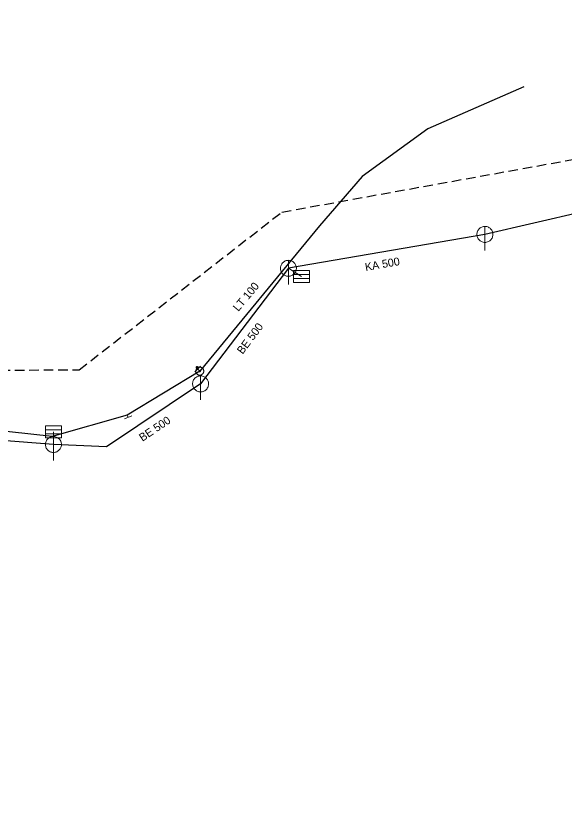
# Model space of a CAD drawing. Extents: x -687013 to -686506, y -973869 to -973672.
# Drawn here: x -686801.2 to -686732.6, y -973770.5 to -973671.6 of the extents above; entities that cross this region are included whole.
import ezdxf

# ---------------------------------------------------------------- set-up
doc = ezdxf.new("R2010")
doc.units = 0
doc.header["$LTSCALE"] = 0.4
doc.linetypes.add('MEDIUM_DASHED', pattern=[4.5, 3, -1.5])
doc.layers.add('1', color=7, linetype='Continuous')
for name, color, linetype, lineweight in [('11', 7, 'Continuous', 13), ('14', 7, 'Continuous', 25), ('17', 7, 'Continuous', 25), ('22', 7, 'Continuous', 13), ('34', 7, 'Continuous', 13), ('47', 7, 'Continuous', 13), ('63', 7, 'MEDIUM_DASHED', 25), ('9', 7, 'Continuous', 13)]:
    doc.layers.add(name, color=color, linetype=linetype, lineweight=lineweight)

msp = doc.modelspace()

# ---------------------------------------------------------------- linework, layer by layer
at = {"layer": '11'}
for p, q in [((-686765.44, -973704.18), (-686767.08, -973703.16)), ((-686796.46, -973723.59), (-686796.46, -973725.17))]:
    msp.add_line(p, q, dxfattribs=at)
at = {"layer": '14'}
for p, q in [((-686704.809, -973690.17), (-686742.511, -973698.919)), ((-686742.511, -973698.919), (-686767.08, -973703.16)), ((-686767.079, -973703.16), (-686778.059, -973717.6)), ((-686796.46, -973725.17), (-686811.199, -973724.039))]:
    msp.add_line(p, q, dxfattribs=at)
at = {"layer": '14', "lineweight": 13}
for p, q in [((-686778.409, -973715.759), (-686778.489, -973715.559)), ((-686778.16, -973716.008), (-686778.409, -973715.759)), ((-686787.234, -973721.504), (-686787.109, -973721.78))]:
    msp.add_line(p, q, dxfattribs=at)
at = {"layer": '14'}
msp.add_lwpolyline([(-686778.059, -973717.6), (-686789.822, -973725.456), (-686796.46, -973725.17)], dxfattribs=at)
at = {"layer": '17'}
for points in [[(-686737.661, -973680.49), (-686749.647, -973685.721), (-686757.875, -973691.668), (-686763.192, -973697.859), (-686778.16, -973716.008)], [(-686778.16, -973716.008), (-686787.234, -973721.504), (-686796.6, -973724.188), (-686817.64, -973721.881), (-686819.859, -973721.829), (-686837.05, -973722.085), (-686859.074, -973725.682), (-686861.337, -973725.804), (-686883.709, -973728.57)]]:
    msp.add_lwpolyline(points, dxfattribs=at)
at = {"layer": '22'}
for p, q in [((-686742.511, -973700.919), (-686742.51, -973697.919)), ((-686767.079, -973705.16), (-686767.078, -973702.16)), ((-686766.451, -973703.923), (-686764.451, -973703.923)), ((-686766.451, -973704.423), (-686764.451, -973704.423)), ((-686778.059, -973719.6), (-686778.058, -973716.6)), ((-686797.471, -973723.333), (-686795.471, -973723.333)), ((-686797.471, -973723.833), (-686795.471, -973723.833)), ((-686796.46, -973727.17), (-686796.459, -973724.17))]:
    msp.add_line(p, q, dxfattribs=at)
for points in [[(-686741.511, -973698.919), (-686741.516, -973698.81), (-686741.534, -973698.702), (-686741.564, -973698.596), (-686741.604, -973698.495), (-686741.656, -973698.398), (-686741.718, -973698.308), (-686741.79, -973698.225), (-686741.87, -973698.151), (-686741.958, -973698.085), (-686742.052, -973698.03), (-686742.152, -973697.985), (-686742.257, -973697.952), (-686742.364, -973697.93), (-686742.473, -973697.92), (-686742.583, -973697.922), (-686742.691, -973697.936), (-686742.798, -973697.961), (-686742.901, -973697.998), (-686742.999, -973698.047), (-686743.091, -973698.105), (-686743.177, -973698.174), (-686743.254, -973698.251), (-686743.323, -973698.337), (-686743.382, -973698.429), (-686743.43, -973698.527), (-686743.467, -973698.63), (-686743.493, -973698.737), (-686743.507, -973698.845), (-686743.51, -973698.955), (-686743.5, -973699.064), (-686743.479, -973699.171), (-686743.445, -973699.275), (-686743.401, -973699.375), (-686743.346, -973699.47), (-686743.28, -973699.558), (-686743.206, -973699.638), (-686743.123, -973699.71), (-686743.033, -973699.772), (-686742.937, -973699.824), (-686742.835, -973699.865), (-686742.73, -973699.895), (-686742.622, -973699.913), (-686742.512, -973699.919), (-686742.403, -973699.913), (-686742.295, -973699.895), (-686742.19, -973699.866), (-686742.088, -973699.825), (-686741.991, -973699.773), (-686741.901, -973699.711), (-686741.818, -973699.64), (-686741.743, -973699.56), (-686741.678, -973699.472), (-686741.622, -973699.378), (-686741.578, -973699.278), (-686741.544, -973699.174), (-686741.522, -973699.066), (-686741.512, -973698.957)], [(-686766.079, -973703.16), (-686766.084, -973703.051), (-686766.102, -973702.943), (-686766.132, -973702.837), (-686766.172, -973702.736), (-686766.224, -973702.639), (-686766.286, -973702.549), (-686766.358, -973702.466), (-686766.438, -973702.392), (-686766.526, -973702.326), (-686766.62, -973702.271), (-686766.72, -973702.226), (-686766.825, -973702.193), (-686766.932, -973702.171), (-686767.041, -973702.161), (-686767.151, -973702.163), (-686767.259, -973702.177), (-686767.366, -973702.202), (-686767.469, -973702.239), (-686767.567, -973702.288), (-686767.659, -973702.346), (-686767.745, -973702.415), (-686767.822, -973702.492), (-686767.891, -973702.578), (-686767.95, -973702.67), (-686767.998, -973702.768), (-686768.035, -973702.871), (-686768.061, -973702.978), (-686768.075, -973703.086), (-686768.078, -973703.196), (-686768.068, -973703.305), (-686768.047, -973703.412), (-686768.013, -973703.516), (-686767.969, -973703.616), (-686767.914, -973703.711), (-686767.848, -973703.799), (-686767.774, -973703.879), (-686767.691, -973703.951), (-686767.601, -973704.013), (-686767.505, -973704.065), (-686767.403, -973704.106), (-686767.298, -973704.136), (-686767.19, -973704.154), (-686767.08, -973704.16), (-686766.971, -973704.154), (-686766.863, -973704.136), (-686766.758, -973704.107), (-686766.656, -973704.066), (-686766.559, -973704.014), (-686766.469, -973703.952), (-686766.386, -973703.881), (-686766.311, -973703.801), (-686766.246, -973703.713), (-686766.19, -973703.619), (-686766.146, -973703.519), (-686766.112, -973703.415), (-686766.09, -973703.307), (-686766.08, -973703.198)], [(-686766.451, -973703.423), (-686764.451, -973703.423), (-686764.451, -973704.923), (-686766.451, -973704.923)], [(-686777.059, -973717.6), (-686777.064, -973717.491), (-686777.082, -973717.383), (-686777.112, -973717.277), (-686777.152, -973717.176), (-686777.204, -973717.079), (-686777.266, -973716.989), (-686777.338, -973716.906), (-686777.418, -973716.832), (-686777.506, -973716.766), (-686777.6, -973716.711), (-686777.7, -973716.666), (-686777.805, -973716.633), (-686777.912, -973716.611), (-686778.021, -973716.601), (-686778.131, -973716.603), (-686778.239, -973716.617), (-686778.346, -973716.642), (-686778.449, -973716.679), (-686778.547, -973716.728), (-686778.639, -973716.786), (-686778.725, -973716.855), (-686778.802, -973716.932), (-686778.871, -973717.018), (-686778.93, -973717.11), (-686778.978, -973717.208), (-686779.015, -973717.311), (-686779.041, -973717.418), (-686779.055, -973717.526), (-686779.058, -973717.636), (-686779.048, -973717.745), (-686779.027, -973717.852), (-686778.993, -973717.956), (-686778.949, -973718.056), (-686778.894, -973718.151), (-686778.828, -973718.239), (-686778.754, -973718.319), (-686778.671, -973718.391), (-686778.581, -973718.453), (-686778.485, -973718.505), (-686778.383, -973718.546), (-686778.278, -973718.576), (-686778.17, -973718.594), (-686778.06, -973718.6), (-686777.951, -973718.594), (-686777.843, -973718.576), (-686777.738, -973718.547), (-686777.636, -973718.506), (-686777.539, -973718.454), (-686777.449, -973718.392), (-686777.366, -973718.321), (-686777.291, -973718.241), (-686777.226, -973718.153), (-686777.17, -973718.059), (-686777.126, -973717.959), (-686777.092, -973717.855), (-686777.07, -973717.747), (-686777.06, -973717.638)], [(-686797.471, -973722.833), (-686795.471, -973722.833), (-686795.471, -973724.333), (-686797.471, -973724.333)], [(-686795.46, -973725.17), (-686795.465, -973725.061), (-686795.483, -973724.953), (-686795.513, -973724.847), (-686795.553, -973724.746), (-686795.605, -973724.649), (-686795.667, -973724.559), (-686795.739, -973724.476), (-686795.819, -973724.402), (-686795.907, -973724.336), (-686796.001, -973724.281), (-686796.101, -973724.236), (-686796.206, -973724.203), (-686796.313, -973724.181), (-686796.422, -973724.171), (-686796.532, -973724.173), (-686796.64, -973724.187), (-686796.747, -973724.212), (-686796.85, -973724.249), (-686796.948, -973724.298), (-686797.04, -973724.356), (-686797.126, -973724.425), (-686797.203, -973724.502), (-686797.272, -973724.588), (-686797.331, -973724.68), (-686797.379, -973724.778), (-686797.416, -973724.881), (-686797.442, -973724.988), (-686797.456, -973725.096), (-686797.459, -973725.206), (-686797.449, -973725.315), (-686797.428, -973725.422), (-686797.394, -973725.526), (-686797.35, -973725.626), (-686797.295, -973725.721), (-686797.229, -973725.809), (-686797.155, -973725.889), (-686797.072, -973725.961), (-686796.982, -973726.023), (-686796.886, -973726.075), (-686796.784, -973726.116), (-686796.679, -973726.146), (-686796.571, -973726.164), (-686796.461, -973726.17), (-686796.352, -973726.164), (-686796.244, -973726.146), (-686796.139, -973726.117), (-686796.037, -973726.076), (-686795.94, -973726.024), (-686795.85, -973725.962), (-686795.767, -973725.891), (-686795.692, -973725.811), (-686795.627, -973725.723), (-686795.571, -973725.629), (-686795.527, -973725.529), (-686795.493, -973725.425), (-686795.471, -973725.317), (-686795.461, -973725.208)]]:
    msp.add_lwpolyline(points, close=True, dxfattribs=at)
at = {"layer": '34'}
for p, q in [((-686778.055, -973715.405), (-686778.762, -973716.112)), ((-686786.653, -973721.574), (-686787.565, -973721.984))]:
    msp.add_line(p, q, dxfattribs=at)
at = {"layer": '47'}
for points in [[(-686777.845, -973715.619), (-686777.887, -973715.588), (-686777.933, -973715.562), (-686777.98, -973715.541), (-686778.03, -973715.525), (-686778.081, -973715.514), (-686778.134, -973715.509), (-686778.186, -973715.509), (-686778.238, -973715.514), (-686778.289, -973715.525), (-686778.339, -973715.541), (-686778.387, -973715.562), (-686778.432, -973715.589), (-686778.474, -973715.619), (-686778.513, -973715.654), (-686778.548, -973715.693), (-686778.579, -973715.735), (-686778.605, -973715.781), (-686778.626, -973715.829), (-686778.642, -973715.878), (-686778.653, -973715.929), (-686778.658, -973715.982), (-686778.659, -973716.035), (-686778.653, -973716.087), (-686778.643, -973716.137), (-686778.626, -973716.187), (-686778.605, -973716.235), (-686778.579, -973716.281), (-686778.548, -973716.322), (-686778.513, -973716.361), (-686778.474, -973716.396), (-686778.432, -973716.427), (-686778.386, -973716.453), (-686778.338, -973716.475), (-686778.289, -973716.49), (-686778.238, -973716.501), (-686778.186, -973716.507), (-686778.133, -973716.507), (-686778.081, -973716.502), (-686778.03, -973716.491), (-686777.98, -973716.474), (-686777.932, -973716.453), (-686777.887, -973716.427), (-686777.845, -973716.396), (-686777.806, -973716.361), (-686777.771, -973716.322), (-686777.74, -973716.28), (-686777.714, -973716.234), (-686777.693, -973716.187), (-686777.677, -973716.137), (-686777.666, -973716.086), (-686777.66, -973716.034), (-686777.66, -973715.982), (-686777.666, -973715.93), (-686777.677, -973715.878), (-686777.693, -973715.828), (-686777.714, -973715.78), (-686777.74, -973715.736), (-686777.771, -973715.693), (-686777.806, -973715.654)], [(-686778.108, -973715.944), (-686778.115, -973715.938), (-686778.122, -973715.935), (-686778.13, -973715.931), (-686778.138, -973715.928), (-686778.147, -973715.927), (-686778.155, -973715.926), (-686778.164, -973715.925), (-686778.172, -973715.926), (-686778.181, -973715.929), (-686778.189, -973715.931), (-686778.197, -973715.935), (-686778.204, -973715.939), (-686778.211, -973715.944), (-686778.218, -973715.949), (-686778.223, -973715.956), (-686778.229, -973715.963), (-686778.232, -973715.97), (-686778.236, -973715.978), (-686778.239, -973715.986), (-686778.24, -973715.995), (-686778.241, -973716.003), (-686778.242, -973716.012), (-686778.241, -973716.02), (-686778.239, -973716.029), (-686778.236, -973716.037), (-686778.232, -973716.045), (-686778.228, -973716.052), (-686778.223, -973716.059), (-686778.218, -973716.066), (-686778.211, -973716.071), (-686778.204, -973716.077), (-686778.197, -973716.08), (-686778.189, -973716.084), (-686778.181, -973716.087), (-686778.172, -973716.088), (-686778.164, -973716.09), (-686778.155, -973716.09), (-686778.147, -973716.089), (-686778.138, -973716.087), (-686778.13, -973716.084), (-686778.122, -973716.08), (-686778.115, -973716.076), (-686778.108, -973716.071), (-686778.101, -973716.066), (-686778.096, -973716.059), (-686778.09, -973716.052), (-686778.087, -973716.045), (-686778.083, -973716.037), (-686778.08, -973716.029), (-686778.079, -973716.02), (-686778.077, -973716.012), (-686778.077, -973716.003), (-686778.078, -973715.995), (-686778.081, -973715.986), (-686778.083, -973715.978), (-686778.087, -973715.97), (-686778.091, -973715.963), (-686778.096, -973715.956), (-686778.101, -973715.949)]]:
    msp.add_lwpolyline(points, close=True, dxfattribs=at)
at = {"layer": '63'}
msp.add_lwpolyline([(-686909.784, -973869.363), (-686968.065, -973779.329), (-686968.065, -973779.329), (-686933.901, -973735.117), (-686933.901, -973735.117), (-686846.279, -973716.226), (-686846.279, -973716.226), (-686793.223, -973715.824), (-686793.223, -973715.824), (-686767.901, -973696.129), (-686767.901, -973696.129), (-686632.047, -973671.611), (-686632.047, -973671.611), (-686619.587, -973774.908), (-686619.587, -973774.908), (-686749.412, -973818.317), (-686749.412, -973818.317)], close=True, dxfattribs=at)
at = {"layer": '9'}
for points in [[(-686778.615, -973715.559), (-686778.615, -973715.572), (-686778.612, -973715.585), (-686778.61, -973715.598), (-686778.605, -973715.61), (-686778.598, -973715.622), (-686778.592, -973715.633), (-686778.583, -973715.643), (-686778.573, -973715.653), (-686778.563, -973715.661), (-686778.553, -973715.668), (-686778.541, -973715.674), (-686778.529, -973715.679), (-686778.516, -973715.682), (-686778.502, -973715.684), (-686778.49, -973715.686), (-686778.477, -973715.685), (-686778.463, -973715.683), (-686778.451, -973715.68), (-686778.438, -973715.675), (-686778.426, -973715.669), (-686778.416, -973715.662), (-686778.406, -973715.654), (-686778.396, -973715.644), (-686778.387, -973715.634), (-686778.38, -973715.623), (-686778.375, -973715.611), (-686778.37, -973715.599), (-686778.367, -973715.586), (-686778.365, -973715.573), (-686778.362, -973715.56), (-686778.364, -973715.547), (-686778.365, -973715.534), (-686778.369, -973715.521), (-686778.374, -973715.509), (-686778.379, -973715.497), (-686778.387, -973715.486), (-686778.394, -973715.476), (-686778.404, -973715.466), (-686778.414, -973715.458), (-686778.426, -973715.451), (-686778.438, -973715.445), (-686778.45, -973715.44), (-686778.463, -973715.437), (-686778.475, -973715.435), (-686778.489, -973715.434), (-686778.502, -973715.434), (-686778.514, -973715.436), (-686778.527, -973715.439), (-686778.539, -973715.444), (-686778.551, -973715.45), (-686778.563, -973715.457), (-686778.573, -973715.465), (-686778.583, -973715.475), (-686778.59, -973715.485), (-686778.598, -973715.496), (-686778.603, -973715.508), (-686778.608, -973715.52), (-686778.612, -973715.533), (-686778.614, -973715.546)], [(-686778.595, -973715.559), (-686778.595, -973715.57), (-686778.593, -973715.581), (-686778.59, -973715.592), (-686778.587, -973715.602), (-686778.581, -973715.612), (-686778.576, -973715.621), (-686778.568, -973715.63), (-686778.561, -973715.638), (-686778.551, -973715.645), (-686778.543, -973715.651), (-686778.532, -973715.656), (-686778.522, -973715.66), (-686778.512, -973715.663), (-686778.5, -973715.666), (-686778.49, -973715.666), (-686778.478, -973715.666), (-686778.468, -973715.664), (-686778.456, -973715.661), (-686778.446, -973715.657), (-686778.436, -973715.652), (-686778.428, -973715.646), (-686778.419, -973715.639), (-686778.411, -973715.631), (-686778.404, -973715.622), (-686778.397, -973715.613), (-686778.392, -973715.603), (-686778.389, -973715.593), (-686778.386, -973715.582), (-686778.384, -973715.571), (-686778.382, -973715.56), (-686778.382, -973715.549), (-686778.384, -973715.538), (-686778.387, -973715.527), (-686778.392, -973715.517), (-686778.397, -973715.507), (-686778.402, -973715.498), (-686778.409, -973715.489), (-686778.418, -973715.481), (-686778.426, -973715.474), (-686778.436, -973715.468), (-686778.446, -973715.463), (-686778.455, -973715.459), (-686778.467, -973715.456), (-686778.477, -973715.454), (-686778.489, -973715.454), (-686778.5, -973715.453), (-686778.511, -973715.455), (-686778.522, -973715.458), (-686778.531, -973715.462), (-686778.541, -973715.467), (-686778.551, -973715.473), (-686778.559, -973715.48), (-686778.568, -973715.488), (-686778.575, -973715.497), (-686778.58, -973715.506), (-686778.585, -973715.516), (-686778.59, -973715.526), (-686778.593, -973715.537), (-686778.595, -973715.548)], [(-686778.576, -973715.559), (-686778.576, -973715.568), (-686778.575, -973715.577), (-686778.571, -973715.586), (-686778.568, -973715.594), (-686778.565, -973715.602), (-686778.559, -973715.61), (-686778.553, -973715.617), (-686778.548, -973715.623), (-686778.541, -973715.629), (-686778.532, -973715.634), (-686778.524, -973715.638), (-686778.517, -973715.641), (-686778.507, -973715.644), (-686778.499, -973715.645), (-686778.49, -973715.647), (-686778.48, -973715.646), (-686778.472, -973715.645), (-686778.463, -973715.642), (-686778.455, -973715.639), (-686778.446, -973715.635), (-686778.438, -973715.63), (-686778.431, -973715.624), (-686778.426, -973715.618), (-686778.419, -973715.611), (-686778.414, -973715.603), (-686778.411, -973715.595), (-686778.407, -973715.587), (-686778.404, -973715.578), (-686778.404, -973715.569), (-686778.401, -973715.56), (-686778.402, -973715.551), (-686778.404, -973715.542), (-686778.406, -973715.533), (-686778.409, -973715.525), (-686778.414, -973715.517), (-686778.419, -973715.509), (-686778.424, -973715.502), (-686778.431, -973715.496), (-686778.438, -973715.49), (-686778.446, -973715.485), (-686778.453, -973715.481), (-686778.462, -973715.478), (-686778.47, -973715.475), (-686778.48, -973715.474), (-686778.489, -973715.473), (-686778.497, -973715.473), (-686778.507, -973715.474), (-686778.516, -973715.477), (-686778.524, -973715.48), (-686778.531, -973715.484), (-686778.539, -973715.489), (-686778.546, -973715.495), (-686778.553, -973715.501), (-686778.558, -973715.508), (-686778.563, -973715.516), (-686778.568, -973715.524), (-686778.571, -973715.532), (-686778.573, -973715.541), (-686778.575, -973715.55)], [(-686778.556, -973715.559), (-686778.556, -973715.566), (-686778.554, -973715.573), (-686778.553, -973715.58), (-686778.551, -973715.586), (-686778.548, -973715.592), (-686778.544, -973715.598), (-686778.539, -973715.604), (-686778.534, -973715.609), (-686778.529, -973715.613), (-686778.522, -973715.617), (-686778.517, -973715.62), (-686778.511, -973715.623), (-686778.504, -973715.624), (-686778.497, -973715.627), (-686778.49, -973715.627), (-686778.482, -973715.627), (-686778.475, -973715.625), (-686778.468, -973715.624), (-686778.463, -973715.621), (-686778.455, -973715.618), (-686778.451, -973715.614), (-686778.445, -973715.61), (-686778.44, -973715.605), (-686778.436, -973715.599), (-686778.431, -973715.593), (-686778.428, -973715.587), (-686778.426, -973715.581), (-686778.424, -973715.574), (-686778.423, -973715.567), (-686778.421, -973715.56), (-686778.421, -973715.553), (-686778.423, -973715.546), (-686778.424, -973715.539), (-686778.428, -973715.533), (-686778.431, -973715.526), (-686778.434, -973715.521), (-686778.438, -973715.515), (-686778.443, -973715.51), (-686778.45, -973715.506), (-686778.455, -973715.502), (-686778.462, -973715.499), (-686778.468, -973715.496), (-686778.475, -973715.494), (-686778.482, -973715.493), (-686778.489, -973715.493), (-686778.495, -973715.493), (-686778.502, -973715.493), (-686778.509, -973715.495), (-686778.516, -973715.498), (-686778.522, -973715.501), (-686778.527, -973715.505), (-686778.534, -973715.509), (-686778.539, -973715.514), (-686778.543, -973715.52), (-686778.546, -973715.525), (-686778.549, -973715.532), (-686778.553, -973715.538), (-686778.553, -973715.545), (-686778.556, -973715.552)], [(-686778.536, -973715.559), (-686778.536, -973715.564), (-686778.536, -973715.569), (-686778.534, -973715.574), (-686778.532, -973715.578), (-686778.531, -973715.583), (-686778.527, -973715.587), (-686778.524, -973715.59), (-686778.521, -973715.594), (-686778.517, -973715.597), (-686778.514, -973715.6), (-686778.509, -973715.602), (-686778.504, -973715.604), (-686778.5, -973715.605), (-686778.495, -973715.607), (-686778.49, -973715.607), (-686778.485, -973715.607), (-686778.48, -973715.606), (-686778.475, -973715.605), (-686778.47, -973715.603), (-686778.465, -973715.601), (-686778.462, -973715.598), (-686778.458, -973715.595), (-686778.455, -973715.591), (-686778.451, -973715.588), (-686778.448, -973715.584), (-686778.446, -973715.579), (-686778.445, -973715.575), (-686778.443, -973715.57), (-686778.443, -973715.565), (-686778.441, -973715.56), (-686778.441, -973715.555), (-686778.443, -973715.55), (-686778.443, -973715.545), (-686778.446, -973715.541), (-686778.448, -973715.536), (-686778.451, -973715.532), (-686778.453, -973715.528), (-686778.456, -973715.525), (-686778.46, -973715.522), (-686778.465, -973715.519), (-686778.47, -973715.517), (-686778.473, -973715.515), (-686778.478, -973715.514), (-686778.483, -973715.513), (-686778.489, -973715.513), (-686778.494, -973715.513), (-686778.499, -973715.514), (-686778.504, -973715.514), (-686778.507, -973715.516), (-686778.512, -973715.518), (-686778.517, -973715.521), (-686778.519, -973715.524), (-686778.524, -973715.527), (-686778.526, -973715.531), (-686778.529, -973715.535), (-686778.531, -973715.54), (-686778.534, -973715.544), (-686778.534, -973715.549), (-686778.536, -973715.554)], [(-686778.516, -973715.559), (-686778.516, -973715.562), (-686778.517, -973715.565), (-686778.516, -973715.567), (-686778.514, -973715.57), (-686778.514, -973715.573), (-686778.512, -973715.575), (-686778.509, -973715.577), (-686778.507, -973715.579), (-686778.505, -973715.581), (-686778.504, -973715.583), (-686778.5, -973715.585), (-686778.497, -973715.586), (-686778.495, -973715.586), (-686778.492, -973715.587), (-686778.49, -973715.587), (-686778.487, -973715.587), (-686778.483, -973715.587), (-686778.48, -973715.586), (-686778.478, -973715.585), (-686778.475, -973715.584), (-686778.473, -973715.582), (-686778.47, -973715.58), (-686778.468, -973715.578), (-686778.468, -973715.576), (-686778.465, -973715.574), (-686778.465, -973715.571), (-686778.463, -973715.568), (-686778.463, -973715.566), (-686778.462, -973715.563), (-686778.46, -973715.56), (-686778.462, -973715.557), (-686778.462, -973715.554), (-686778.463, -973715.551), (-686778.463, -973715.549), (-686778.465, -973715.546), (-686778.467, -973715.544), (-686778.468, -973715.541), (-686778.47, -973715.539), (-686778.473, -973715.538), (-686778.475, -973715.536), (-686778.477, -973715.535), (-686778.48, -973715.534), (-686778.482, -973715.533), (-686778.485, -973715.533), (-686778.489, -973715.532), (-686778.492, -973715.533), (-686778.495, -973715.532), (-686778.497, -973715.534), (-686778.5, -973715.534), (-686778.502, -973715.535), (-686778.504, -973715.537), (-686778.507, -973715.538), (-686778.509, -973715.54), (-686778.511, -973715.543), (-686778.512, -973715.545), (-686778.514, -973715.548), (-686778.514, -973715.55), (-686778.516, -973715.553), (-686778.516, -973715.556)], [(-686778.497, -973715.559), (-686778.497, -973715.561), (-686778.497, -973715.561), (-686778.495, -973715.561), (-686778.495, -973715.563), (-686778.497, -973715.564), (-686778.495, -973715.564), (-686778.495, -973715.564), (-686778.495, -973715.566), (-686778.495, -973715.566), (-686778.494, -973715.567), (-686778.492, -973715.567), (-686778.492, -973715.567), (-686778.492, -973715.568), (-686778.49, -973715.568), (-686778.49, -973715.568), (-686778.489, -973715.568), (-686778.487, -973715.568), (-686778.487, -973715.567), (-686778.487, -973715.567), (-686778.485, -973715.567), (-686778.485, -973715.566), (-686778.485, -973715.566), (-686778.483, -973715.565), (-686778.483, -973715.565), (-686778.482, -973715.564), (-686778.482, -973715.563), (-686778.48, -973715.562), (-686778.48, -973715.562), (-686778.48, -973715.561), (-686778.48, -973715.56), (-686778.48, -973715.559), (-686778.48, -973715.558), (-686778.48, -973715.558), (-686778.482, -973715.557), (-686778.482, -973715.556), (-686778.482, -973715.555), (-686778.482, -973715.555), (-686778.483, -973715.554), (-686778.483, -973715.554), (-686778.485, -973715.553), (-686778.485, -973715.553), (-686778.487, -973715.552), (-686778.487, -973715.552), (-686778.487, -973715.552), (-686778.489, -973715.552), (-686778.49, -973715.552), (-686778.49, -973715.552), (-686778.49, -973715.552), (-686778.492, -973715.553), (-686778.492, -973715.552), (-686778.494, -973715.554), (-686778.494, -973715.554), (-686778.495, -973715.554), (-686778.495, -973715.554), (-686778.495, -973715.556), (-686778.495, -973715.557), (-686778.495, -973715.558), (-686778.497, -973715.558), (-686778.497, -973715.559)]]:
    msp.add_lwpolyline(points, close=True, dxfattribs=at)

# ---------------------------------------------------------------- texts
at = {"layer": '1'}
for s, rotation, p in [('KA 500', 10, (-686757.413, -973703.506)), ('LT 100', 50, (-686773.345, -973708.62)), ('BE 500', 53, (-686772.804, -973713.969)), ('BE 500', 34, (-686785.332, -973724.845))]:
    msp.add_text(s, height=1, rotation=rotation, dxfattribs=at).set_placement(p)

doc.saveas('drawing.dxf')
